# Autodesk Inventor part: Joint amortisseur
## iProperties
Created: 2011-01
Part Number: Joint amortisseur
Document SubType Name: Modeling
Designer: eric
Density: 1 g/cm^3
Mass: 1.19446 g
Surface Area: 26.7879 cm^2
Volume: 1.19446 cm^3
Author: eric
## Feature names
1. Base1
